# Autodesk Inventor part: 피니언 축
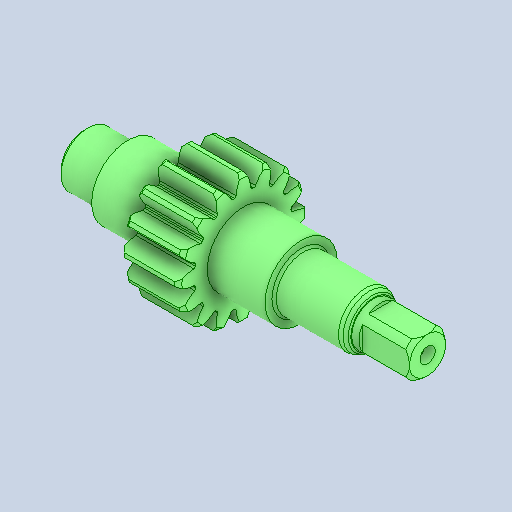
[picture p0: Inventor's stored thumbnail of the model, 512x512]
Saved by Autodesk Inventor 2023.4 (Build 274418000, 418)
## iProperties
Created: 2024-10
Part Number: 피니언 축
Material: 강철, 탄소
Document SubType Name: Modeling
Designer: EDU
Density: 7.85 g/cm^3
Appearance: 기본값
Author: jhkim
Sending System: Autodesk Inventor 2025
Preprocessor: ST-DEVELOPER v20
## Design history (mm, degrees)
node "피니언 축1"
node "솔리드2"
node "솔리드1"
